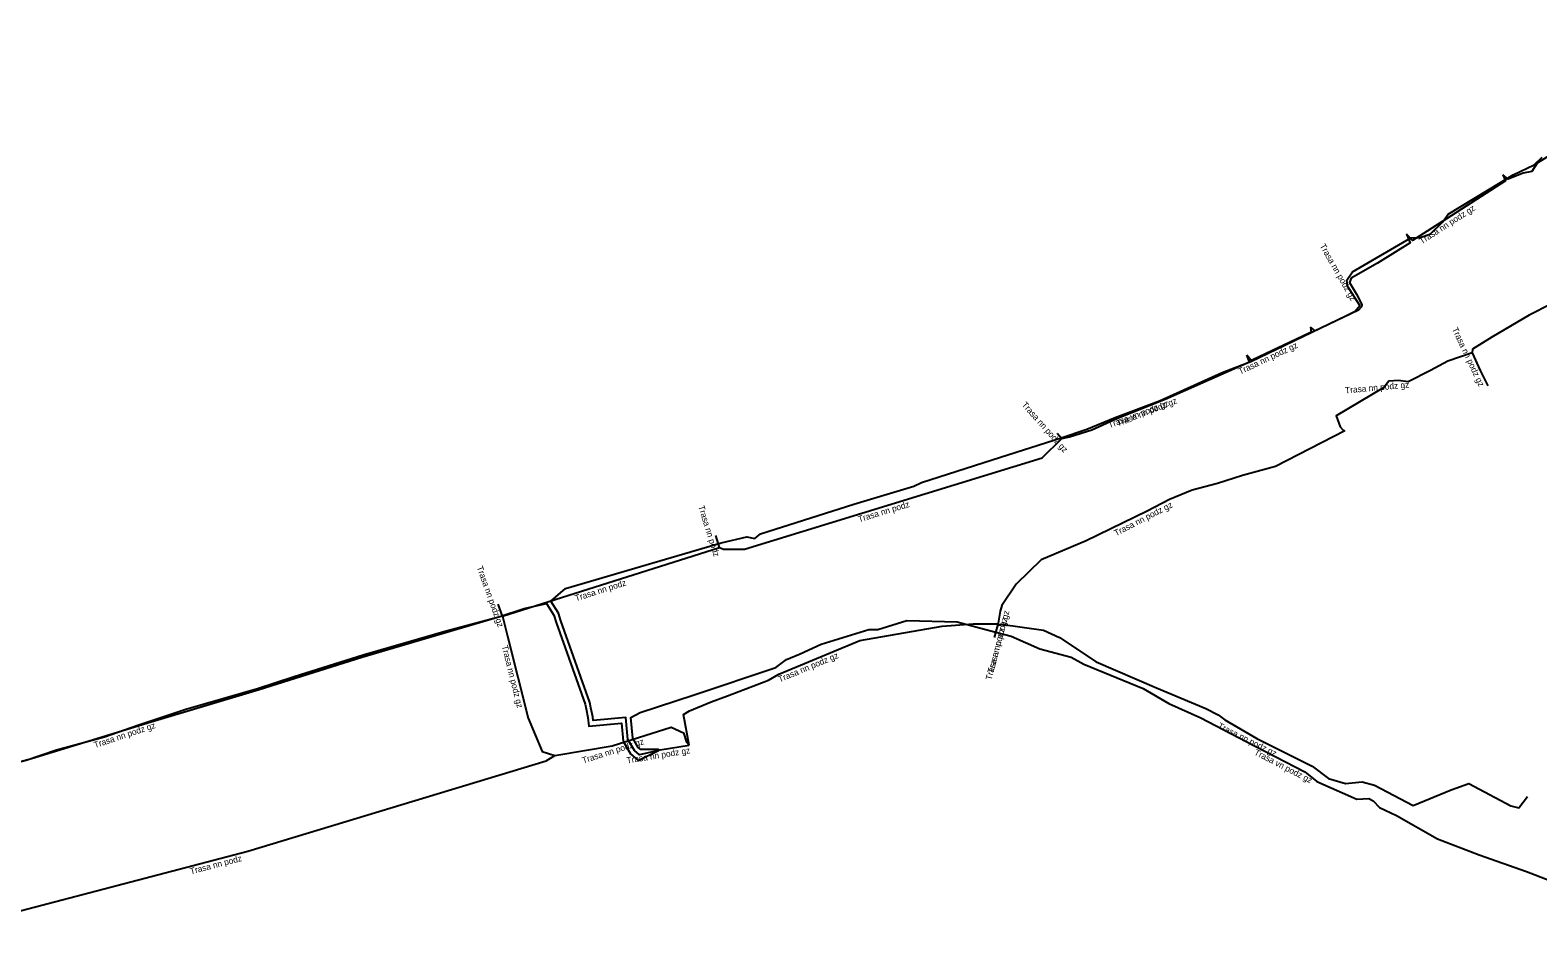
# Model space of a CAD drawing. Extents: x -687924 to -686708, y -1056742 to -1056249.
# Drawn here: x -687719.7 to -687598.7, y -1056656.5 to -1056583.1 of the extents above; entities that cross this region are included whole.
import ezdxf

# ---------------------------------------------------------------- set-up
doc = ezdxf.new("R2010")
doc.units = 0
for name, color, linetype in [('Popiskový text - Ostatní atributy Trasy', 7, 'Continuous'), ('Spojnice NN', 7, 'Continuous'), ('Spojnice VN', 7, 'Continuous')]:
    doc.layers.add(name, color=color, linetype=linetype)

msp = doc.modelspace()

# ---------------------------------------------------------------- linework, layer by layer
at = {"layer": 'Spojnice NN'}
for points in [[(-687577.6, -1056583.1), (-687581.29, -1056585.41), (-687585.15, -1056587.74), (-687586.96, -1056588.7), (-687587.72, -1056589.18), (-687594.63, -1056593.05), (-687594.85, -1056592.97), (-687595.19, -1056592.46), (-687595.58, -1056591.82), (-687598.75, -1056593.78), (-687599.17, -1056594.44), (-687599.88, -1056594.58), (-687601.07, -1056595.06), (-687601.5, -1056594.72)], [(-687601.5, -1056594.72), (-687601.28, -1056595.19), (-687606.02, -1056598.24), (-687608.76, -1056599.98), (-687609.24, -1056599.47)], [(-687585.07, -1056597.97), (-687585.45, -1056597.61), (-687591.64, -1056601.13), (-687592.37, -1056601.39), (-687595.77, -1056603.62), (-687597.6, -1056605.08), (-687599.38, -1056605.98), (-687602.39, -1056607.73), (-687603.93, -1056608.7), (-687603.97, -1056609.01)], [(-687609.24, -1056599.47), (-687608.95, -1056600.16), (-687611.56, -1056601.79), (-687613.68, -1056603), (-687613.8, -1056603.35), (-687613.26, -1056604.3), (-687612.83, -1056605.12), (-687612.84, -1056605.31), (-687613.08, -1056605.58), (-687616.12, -1056607.01), (-687616.57, -1056607.23), (-687616.95, -1056606.94)], [(-687616.95, -1056606.94), (-687616.88, -1056607.35), (-687617.04, -1056607.43), (-687621.56, -1056609.55), (-687621.72, -1056609.58), (-687622.06, -1056609.18)], [(-687636.9, -1056615.89), (-687636.29, -1056615.74), (-687634.49, -1056615.17), (-687632.43, -1056614.24), (-687628.62, -1056612.73), (-687621.85, -1056609.73), (-687622.06, -1056609.18)], [(-687603.97, -1056609.01), (-687605.92, -1056609.66), (-687607.31, -1056610.42), (-687609.1, -1056611.32), (-687609.88, -1056611.21), (-687610.64, -1056611.28), (-687611.05, -1056611.77), (-687614.89, -1056614.07), (-687614.56, -1056614.93), (-687614.35, -1056615.18), (-687614.18, -1056615.25)], [(-687603.97, -1056609.01), (-687603.31, -1056610.42), (-687602.7, -1056611.65)], [(-687614.18, -1056615.25), (-687619.74, -1056618.12), (-687622.4, -1056618.84), (-687624.4, -1056619.49), (-687626.45, -1056620.03), (-687628.26, -1056620.78), (-687630.06, -1056621.71), (-687634.96, -1056624.09), (-687638.56, -1056625.61), (-687640.58, -1056627.58), (-687641.71, -1056629.27), (-687641.86, -1056629.74), (-687642.02, -1056630.69), (-687642.03, -1056630.74)], [(-687664.39, -1056624.62), (-687664.05, -1056624.76), (-687662.37, -1056624.75), (-687638.49, -1056617.44), (-687636.9, -1056615.89)], [(-687637.29, -1056615.45), (-687636.9, -1056615.89)], [(-687664.39, -1056624.62), (-687664.69, -1056623.66)], [(-687681.8, -1056630.14), (-687664.39, -1056624.62)], [(-687681.8, -1056630.14), (-687682.14, -1056629.18)], [(-687681.8, -1056630.14), (-687686.32, -1056631.34), (-687692.99, -1056633.26), (-687698.53, -1056635), (-687701.46, -1056635.96), (-687707.22, -1056637.63), (-687711.08, -1056638.91), (-687713.76, -1056639.84), (-687717.6, -1056640.89), (-687720.05, -1056641.72), (-687725.49, -1056643.05), (-687726.71, -1056643.5), (-687732.46, -1056644.89), (-687736.79, -1056645.99), (-687740.43, -1056646.92)], [(-687681.8, -1056630.14), (-687681.4, -1056631.74), (-687679.75, -1056638.33), (-687678.61, -1056640.99), (-687677.6, -1056641.33)], [(-687666.83, -1056640.5), (-687667.26, -1056638.03), (-687666.8, -1056637.73), (-687665.04, -1056637.02), (-687663.73, -1056636.54), (-687660.46, -1056635.28), (-687659.63, -1056634.79), (-687653.13, -1056632.08), (-687646.5, -1056630.93), (-687644.03, -1056630.74), (-687642.03, -1056630.74)], [(-687642.07, -1056630.9), (-687642.33, -1056631.86)], [(-687642.03, -1056630.74), (-687642.07, -1056630.9)], [(-687642.07, -1056630.9), (-687642.05, -1056630.89), (-687641.79, -1056630.78), (-687638.37, -1056631.27), (-687637.1, -1056631.86), (-687634.15, -1056633.81), (-687629.29, -1056635.89), (-687625.34, -1056637.55), (-687624.34, -1056638.05), (-687623.83, -1056638.47), (-687621.25, -1056639.96), (-687616.81, -1056642.18), (-687615.49, -1056643.17), (-687614.13, -1056643.58), (-687612.78, -1056643.43), (-687611.8, -1056643.71), (-687608.7, -1056645.34), (-687605.65, -1056644.08), (-687604.23, -1056643.58), (-687600.86, -1056645.35), (-687600.21, -1056645.53), (-687599.51, -1056644.6)], [(-687677.6, -1056641.33), (-687673, -1056640.55), (-687668.26, -1056639.04), (-687667.27, -1056639.5), (-687667.03, -1056640.26), (-687666.83, -1056640.5)], [(-687669.29, -1056640.85), (-687669.14, -1056640.88), (-687666.83, -1056640.5)], [(-687730.6, -1056656.52), (-687726.58, -1056655.38), (-687702.24, -1056649), (-687678.29, -1056641.75), (-687677.6, -1056641.33)]]:
    msp.add_lwpolyline(points, dxfattribs=at)
at = {"layer": 'Spojnice VN'}
for points in [[(-687669.26, -1056640.91), (-687669.26, -1056640.92), (-687669.29, -1056640.92), (-687670.8, -1056641.28), (-687671.21, -1056640.93), (-687671.73, -1056640.05), (-687671.9, -1056638.28), (-687674.52, -1056638.52), (-687674.55, -1056638.21), (-687674.7, -1056637.5), (-687674.79, -1056637.08), (-687677.11, -1056630.52), (-687677.32, -1056629.89), (-687677.91, -1056628.94), (-687676.74, -1056627.91), (-687664.26, -1056624.24), (-687662.19, -1056623.78), (-687661.56, -1056623.91), (-687661.09, -1056623.54), (-687653.59, -1056621.15), (-687648.79, -1056619.7), (-687648.18, -1056619.41), (-687642.49, -1056617.59), (-687636.88, -1056615.79), (-687634.9, -1056615.12), (-687632.62, -1056614.2), (-687629.07, -1056612.85), (-687624.02, -1056610.59), (-687621.72, -1056609.69), (-687614.05, -1056606), (-687613.35, -1056605.65), (-687612.97, -1056605.19), (-687613.97, -1056603.66), (-687614.03, -1056603.17), (-687613.58, -1056602.51), (-687608.89, -1056599.77), (-687608.11, -1056599.75), (-687607.3, -1056599.46), (-687606.35, -1056598.5), (-687605.89, -1056597.86), (-687600.66, -1056594.7), (-687598.98, -1056593.9), (-687598.35, -1056593.3)], [(-687726.82, -1056643.52), (-687719.62, -1056641.55), (-687710, -1056638.63), (-687701.34, -1056636.02), (-687693.1, -1056633.44), (-687682.03, -1056630.16), (-687680.05, -1056629.53), (-687678.26, -1056629.12), (-687677.69, -1056630.07), (-687677.49, -1056630.65), (-687675.17, -1056637.19), (-687675.09, -1056637.58), (-687674.95, -1056638.27), (-687674.88, -1056638.96), (-687672.26, -1056638.72), (-687672.12, -1056640.18), (-687671.52, -1056641.2), (-687670.9, -1056641.72), (-687669.29, -1056640.92), (-687669.25, -1056640.92), (-687669.25, -1056640.91)], [(-687669.29, -1056640.85), (-687670.7, -1056640.84), (-687670.9, -1056640.67), (-687671.34, -1056639.92), (-687671.5, -1056638.27), (-687670.76, -1056637.87), (-687666.41, -1056636.46), (-687659.85, -1056634.26), (-687659.01, -1056633.61), (-687657.92, -1056633.16), (-687656.23, -1056632.38), (-687652.4, -1056631.21), (-687651.67, -1056631.22), (-687649.35, -1056630.48), (-687645.3, -1056630.6), (-687642.7, -1056631.3), (-687640.96, -1056631.75), (-687638.67, -1056632.77), (-687636.14, -1056633.44), (-687635.14, -1056633.99), (-687630.37, -1056635.94), (-687628.32, -1056637.15), (-687625.74, -1056638.29), (-687622.11, -1056640.19), (-687617.39, -1056642.62), (-687616.42, -1056643.41), (-687613.22, -1056644.82), (-687612.27, -1056644.77), (-687611.9, -1056644.97), (-687611.41, -1056645.49), (-687610.04, -1056646.14), (-687606.74, -1056648.02), (-687603.41, -1056649.3), (-687599.59, -1056650.62), (-687593.98, -1056652.79)]]:
    msp.add_lwpolyline(points, dxfattribs=at)

# ---------------------------------------------------------------- texts
at = {"layer": 'Popiskový text - Ostatní atributy Trasy'}
for s, rotation, p in [('Trasa nn podz gz', 32.7597, (-687608.01, -1056600.3)), ('Trasa nn podz gz', 299.6148, (-687616.22, -1056600.41)), ('Trasa nn podz gz', 295.1835, (-687605.6, -1056607.09)), ('Trasa nn podz gz', 25.1278, (-687622.59, -1056610.75)), ('Trasa nn podz gz', 5.2624, (-687614.14, -1056612.26)), ('Trasa nn podz gz', 21.6197, (-687632.41, -1056614.93)), ('Trasa nn podz gz', 311.5526, (-687640.16, -1056613.19)), ('Trasa vn podz gz', 20.7343, (-687633.07, -1056615.06)), ('Trasa nn podz', 287.354, (-687666.1, -1056621.33)), ('Trasa nn podz', 17.0201, (-687653.17, -1056622.61)), ('Trasa nn podz gz', 27.3239, (-687632.55, -1056623.73)), ('Trasa nn podz gz', 289.5784, (-687683.88, -1056626.21)), ('Trasa nn podz', 17.5934, (-687675.9, -1056628.95)), ('Trasa nn podz gz', 75.4464, (-687642.4, -1056634.75)), ('Trasa nn podz gz', 75.4291, (-687642.55, -1056635.31)), ('Trasa nn podz gz', 284.0547, (-687681.87, -1056632.54)), ('Trasa nn podz gz', 22.6332, (-687659.55, -1056635.46)), ('Trasa nn podz gz', 18.3725, (-687714.51, -1056640.73)), ('Trasa nn podz gz', 333.4375, (-687624.43, -1056639.1)), ('Trasa nn podz gz', 17.6701, (-687675.32, -1056641.97)), ('Trasa nn podz gz', 9.3087, (-687671.8, -1056641.97)), ('Trasa vn podz gz', 332.7839, (-687621.51, -1056641.23)), ('Trasa nn podz', 14.6879, (-687706.82, -1056650.87))]:
    msp.add_text(s, height=0.5, rotation=rotation, dxfattribs=at).set_placement(p)

doc.saveas('drawing.dxf')
